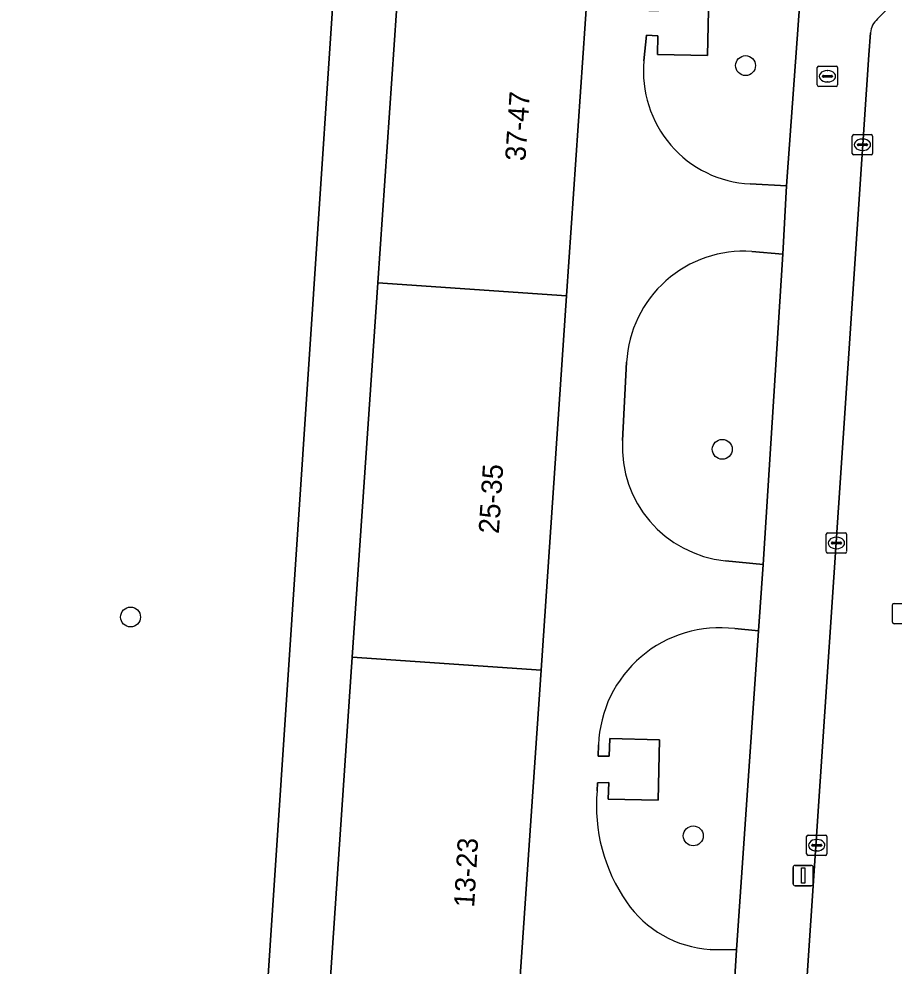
# Model space of a CAD drawing. Extents: x 161848 to 162726, y 385382 to 386521.
# Drawn here: x 162230.99 to 162273.99, y 385418.26 to 385464.81 of the extents above; entities that cross this region are included whole.
import ezdxf

# ---------------------------------------------------------------- set-up
doc = ezdxf.new("R2010")
doc.units = 0
for name, color, linetype in [('IMGEO_Boom', 7, 'Continuous'), ('IMGEO_Brandkraan', 7, 'Continuous'), ('IMGEO_Groenvoorziening', 7, 'Continuous'), ('IMGEO_Kolk', 7, 'Continuous'), ('IMGEO_Lichtmast', 7, 'Continuous'), ('IMGEO_Pand', 7, 'Continuous'), ('IMGEO_Pand_nummerreeks', 7, 'Continuous'), ('IMGEO_Rijbaan_lokaal_open', 7, 'Continuous'), ('IMGEO_Rioolput', 7, 'Continuous'), ('IMGEO_Voetpad_open', 7, 'Continuous')]:
    doc.layers.add(name, color=color, linetype=linetype)

msp = doc.modelspace()

# ---------------------------------------------------------------- linework, layer by layer
at = {"layer": 'IMGEO_Boom'}
for centre in [(162266.695, 385462.519), (162265.549, 385443.66), (162236.471, 385435.417), (162264.124, 385424.661)]:
    msp.add_circle(centre, 0.489, dxfattribs=at)
at = {"layer": 'IMGEO_Brandkraan'}
for p, q in [((162270.218, 385461.567), (162270.218, 385462.419)), ((162270.293, 385462.493), (162271.145, 385462.493)), ((162270.706, 385462.273), (162270.731, 385462.273)), ((162271.219, 385462.419), (162271.219, 385461.567)), ((162270.477, 385461.987), (162270.477, 385461.999)), ((162270.915, 385461.95), (162270.517, 385461.95)), ((162270.52, 385462.036), (162270.918, 385462.036)), ((162270.729, 385461.713), (162270.704, 385461.713)), ((162270.961, 385461.999), (162270.961, 385461.987)), ((162271.145, 385461.493), (162270.293, 385461.493))]:
    msp.add_line(p, q, dxfattribs=at)
for points in [[(162270.218, 385461.567), (162270.218, 385462.419)], [(162270.293, 385462.493), (162271.145, 385462.493)], [(162271.219, 385462.419), (162271.219, 385461.567)], [(162271.145, 385461.493), (162270.293, 385461.493)]]:
    msp.add_lwpolyline(points, dxfattribs=at)
for centre, radius, start, end in [((162270.295, 385462.417), 0.0765, 91.552, 178.448), ((162270.295, 385462.417), 0.0765, 91.552, 178.448), ((162271.143, 385462.417), 0.0765, 1.552, 88.448), ((162271.143, 385462.417), 0.0765, 1.552, 88.448), ((162270.517, 385461.996), 0.0403, 85.8775, 175.7526), ((162270.514, 385461.986), 0.0366, 178.938, 274.7102), ((162270.918, 385461.993), 0.043, 264.8664, 352.4533), ((162270.922, 385461.998), 0.0386, 1.7309, 96.639), ((162270.295, 385461.569), 0.0765, 181.552, 268.448), ((162270.295, 385461.569), 0.0765, 181.552, 268.448), ((162271.143, 385461.569), 0.0765, 271.552, 358.448), ((162271.143, 385461.569), 0.0765, 271.552, 358.448)]:
    msp.add_arc(centre, radius, start, end, dxfattribs=at)
for centre, major_axis, ratio, start_param, end_param in [((162270.705, 385461.993), (-0.387, 0.002), 0.722429, 4.712389, 7.853982), ((162270.73, 385461.993), (-0.39, 0.002), 0.717154, 1.570796, 4.712389)]:
    msp.add_ellipse(centre, major_axis=major_axis, ratio=ratio, start_param=start_param, end_param=end_param, dxfattribs=at)
at = {"layer": 'IMGEO_Groenvoorziening'}
for points in [[(162227.271, 385391.248), (162241.486, 385391.457), (162250.499, 385527.157), (162261.965, 385526.444), (162262.479, 385534.283), (162237.367, 385535.933)], [(162266.924, 385456.7), (162268.704, 385456.607), (162269.753, 385471.068)], [(162262.029, 385466.193), (162261.937, 385465.228), (162262.419, 385465.208), (162262.439, 385466.033), (162264.889, 385465.975), (162264.819, 385463.01), (162262.368, 385463.068), (162262.39, 385463.989), (162261.82, 385464.01), (162261.7, 385462.758)], [(162265.711, 385438.182), (162267.563, 385437.996), (162268.527, 385453.246), (162266.997, 385453.383)], [(162260.848, 385447.937), (162260.642, 385444.097)], [(162264.948, 385419.073), (162266.246, 385419.052), (162267.337, 385434.743)], [(162267.337, 385434.743), (162266.167, 385434.846)], [(162259.467, 385429.143), (162259.45, 385428.574), (162259.999, 385428.573), (162260.02, 385429.446), (162262.468, 385429.388), (162262.397, 385426.41), (162259.949, 385426.468), (162259.968, 385427.283), (162259.41, 385427.271), (162259.398, 385426.87)]]:
    msp.add_lwpolyline(points, dxfattribs=at)
for centre, radius, start, end in [((162267.21, 385462.228), 5.535, 174.5052, 267.0392), ((162266.607, 385447.629), 5.767, 86.1251, 176.9358), ((162266.276, 385443.795), 5.642, 176.936, 264.2555), ((162265.435, 385428.918), 5.973, 82.9641, 177.8444), ((162267.609, 385426.129), 8.244, 174.8464, 214.8948), ((162265.34, 385424.524), 5.465, 214.6978, 265.8847)]:
    msp.add_arc(centre, radius, start, end, dxfattribs=at)
at = {"layer": 'IMGEO_Kolk'}
for p, q in [((162271.938, 385458.203), (162271.938, 385459.055)), ((162272.013, 385459.129), (162272.865, 385459.129)), ((162272.426, 385458.909), (162272.451, 385458.909)), ((162272.939, 385459.055), (162272.939, 385458.203)), ((162272.197, 385458.623), (162272.197, 385458.635)), ((162272.635, 385458.586), (162272.237, 385458.586)), ((162272.24, 385458.672), (162272.638, 385458.672)), ((162272.449, 385458.349), (162272.424, 385458.349)), ((162272.681, 385458.635), (162272.681, 385458.623)), ((162272.865, 385458.129), (162272.013, 385458.129)), ((162270.66, 385438.629), (162270.66, 385439.481)), ((162270.735, 385439.555), (162271.587, 385439.555)), ((162271.148, 385439.335), (162271.173, 385439.335)), ((162271.661, 385439.481), (162271.661, 385438.629)), ((162270.919, 385439.049), (162270.919, 385439.061)), ((162271.357, 385439.012), (162270.959, 385439.012)), ((162270.962, 385439.098), (162271.36, 385439.098)), ((162271.403, 385439.061), (162271.403, 385439.049)), ((162271.587, 385438.555), (162270.735, 385438.555)), ((162271.171, 385438.775), (162271.146, 385438.775)), ((162269.693, 385423.774), (162269.693, 385424.626)), ((162269.768, 385424.7), (162270.62, 385424.7)), ((162270.181, 385424.48), (162270.206, 385424.48)), ((162270.694, 385424.626), (162270.694, 385423.774)), ((162269.952, 385424.194), (162269.952, 385424.206)), ((162270.39, 385424.157), (162269.992, 385424.157)), ((162269.995, 385424.243), (162270.393, 385424.243)), ((162270.204, 385423.92), (162270.179, 385423.92)), ((162270.436, 385424.206), (162270.436, 385424.194)), ((162270.62, 385423.7), (162269.768, 385423.7))]:
    msp.add_line(p, q, dxfattribs=at)
for points in [[(162271.938, 385458.203), (162271.938, 385459.055)], [(162272.013, 385459.129), (162272.865, 385459.129)], [(162272.939, 385459.055), (162272.939, 385458.203)], [(162272.865, 385458.129), (162272.013, 385458.129)], [(162270.66, 385438.629), (162270.66, 385439.481)], [(162270.735, 385439.555), (162271.587, 385439.555)], [(162271.661, 385439.481), (162271.661, 385438.629)], [(162271.587, 385438.555), (162270.735, 385438.555)], [(162269.693, 385423.774), (162269.693, 385424.626)], [(162269.768, 385424.7), (162270.62, 385424.7)], [(162270.694, 385424.626), (162270.694, 385423.774)], [(162270.62, 385423.7), (162269.768, 385423.7)]]:
    msp.add_lwpolyline(points, dxfattribs=at)
for centre, radius, start, end in [((162272.015, 385459.053), 0.0765, 91.552, 178.448), ((162272.015, 385459.053), 0.0765, 91.552, 178.448), ((162272.863, 385459.053), 0.0765, 1.552, 88.448), ((162272.863, 385459.053), 0.0765, 1.552, 88.448), ((162272.237, 385458.632), 0.0403, 85.8775, 175.7526), ((162272.234, 385458.622), 0.0366, 178.938, 274.7102), ((162272.638, 385458.629), 0.043, 264.8664, 352.4533), ((162272.642, 385458.634), 0.0386, 1.7309, 96.639), ((162272.015, 385458.205), 0.0765, 181.552, 268.448), ((162272.015, 385458.205), 0.0765, 181.552, 268.448), ((162272.863, 385458.205), 0.0765, 271.552, 358.448), ((162272.863, 385458.205), 0.0765, 271.552, 358.448), ((162270.737, 385439.479), 0.0765, 91.552, 178.448), ((162270.737, 385439.479), 0.0765, 91.552, 178.448), ((162271.585, 385439.479), 0.0765, 1.552, 88.448), ((162271.585, 385439.479), 0.0765, 1.552, 88.448), ((162270.959, 385439.058), 0.0403, 85.8775, 175.7526), ((162270.956, 385439.048), 0.0366, 178.938, 274.7102), ((162271.36, 385439.055), 0.043, 264.8664, 352.4533), ((162271.364, 385439.06), 0.0386, 1.7309, 96.639), ((162270.737, 385438.631), 0.0765, 181.552, 268.448), ((162270.737, 385438.631), 0.0765, 181.552, 268.448), ((162271.585, 385438.631), 0.0765, 271.552, 358.448), ((162271.585, 385438.631), 0.0765, 271.552, 358.448), ((162269.77, 385424.624), 0.0765, 91.552, 178.448), ((162269.77, 385424.624), 0.0765, 91.552, 178.448), ((162270.618, 385424.624), 0.0765, 1.552, 88.448), ((162270.618, 385424.624), 0.0765, 1.552, 88.448), ((162269.992, 385424.203), 0.0403, 85.8775, 175.7526), ((162269.989, 385424.193), 0.0366, 178.938, 274.7102), ((162270.393, 385424.2), 0.043, 264.8664, 352.4533), ((162270.397, 385424.205), 0.0386, 1.7309, 96.639), ((162269.77, 385423.776), 0.0765, 181.552, 268.448), ((162269.77, 385423.776), 0.0765, 181.552, 268.448), ((162270.618, 385423.776), 0.0765, 271.552, 358.448), ((162270.618, 385423.776), 0.0765, 271.552, 358.448)]:
    msp.add_arc(centre, radius, start, end, dxfattribs=at)
for centre, major_axis, ratio, start_param, end_param in [((162272.425, 385458.629), (-0.387, 0.002), 0.722429, 4.712389, 7.853982), ((162272.45, 385458.629), (-0.39, 0.002), 0.717154, 1.570796, 4.712389), ((162271.147, 385439.055), (-0.387, 0.002), 0.722429, 4.712389, 7.853982), ((162271.172, 385439.055), (-0.39, 0.002), 0.717154, 1.570796, 4.712389), ((162270.18, 385424.2), (-0.387, 0.002), 0.722429, 4.712389, 7.853982), ((162270.205, 385424.2), (-0.39, 0.002), 0.717154, 1.570796, 4.712389)]:
    msp.add_ellipse(centre, major_axis=major_axis, ratio=ratio, start_param=start_param, end_param=end_param, dxfattribs=at)
at = {"layer": 'IMGEO_Lichtmast'}
for p, q in [((162269.03, 385422.309), (162269.03, 385423.109)), ((162269.03, 385423.109), (162269.03, 385422.309)), ((162269.13, 385423.209), (162269.92, 385423.209)), ((162269.92, 385423.209), (162269.13, 385423.209)), ((162270.02, 385423.109), (162270.02, 385422.309)), ((162270.02, 385422.309), (162270.02, 385423.109)), ((162269.92, 385422.209), (162269.13, 385422.209)), ((162269.13, 385422.209), (162269.92, 385422.209))]:
    msp.add_line(p, q, dxfattribs=at)
msp.add_lwpolyline([(162269.45, 385423.084), (162269.6, 385423.084), (162269.6, 385422.334), (162269.45, 385422.334), (162269.45, 385423.084)], dxfattribs=at)
for centre, start, end in [((162269.13, 385423.109), 90, 180), ((162269.13, 385423.109), 90, 180), ((162269.92, 385423.109), 0, 90), ((162269.92, 385423.109), 360, 90), ((162269.13, 385422.309), 180, 270), ((162269.13, 385422.309), 180, 270), ((162269.92, 385422.309), 270, 0), ((162269.92, 385422.309), 270, 0)]:
    msp.add_arc(centre, 0.1, start, end, dxfattribs=at)
at = {"layer": 'IMGEO_Pand'}
for points in [[(162259.156, 385469.606), (162249.879, 385470.239), (162248.624, 385451.841), (162257.902, 385451.209)], [(162257.902, 385451.209), (162248.624, 385451.841), (162247.369, 385433.444), (162256.647, 385432.811)], [(162256.647, 385432.811), (162247.369, 385433.444), (162246.114, 385415.046), (162255.393, 385414.414)]]:
    msp.add_lwpolyline(points, close=True, dxfattribs=at)
at = {"layer": 'IMGEO_Rijbaan_lokaal_open'}
for points in [[(162273.988, 385465.604), (162273.176, 385464.812)], [(162272.835, 385464.128), (162272.75, 385463.047), (162268.862, 385405.077)]]:
    msp.add_lwpolyline(points, dxfattribs=at)
msp.add_arc((162273.826, 385464.061), 0.993, 130.8692, 176.1348, dxfattribs=at)
at = {"layer": 'IMGEO_Rioolput'}
for p, q in [((162273.917, 385435.163), (162273.917, 385436.015)), ((162273.992, 385436.089), (162274.844, 385436.089)), ((162274.844, 385435.089), (162273.992, 385435.089))]:
    msp.add_line(p, q, dxfattribs=at)
for points in [[(162273.917, 385435.163), (162273.917, 385436.015)], [(162273.992, 385436.089), (162274.844, 385436.089)], [(162274.844, 385435.089), (162273.992, 385435.089)]]:
    msp.add_lwpolyline(points, dxfattribs=at)
for centre, start, end in [((162273.994, 385436.013), 91.552, 178.448), ((162273.994, 385436.013), 91.552, 178.448), ((162273.994, 385435.165), 181.552, 268.448), ((162273.994, 385435.165), 181.552, 268.448)]:
    msp.add_arc(centre, 0.0765, start, end, dxfattribs=at)
at = {"layer": 'IMGEO_Voetpad_open'}
for points in [[(162265.497, 385518.248), (162265.529, 385518.79), (162265.893, 385518.768), (162265.834, 385517.933), (162268.677, 385517.734), (162268.891, 385520.791), (162266.048, 385520.989), (162265.98, 385520.017), (162265.602, 385520.039), (162265.961, 385526.178), (162262.952, 385526.381), (162263.466, 385534.217), (162262.479, 385534.283), (162261.965, 385526.444), (162250.499, 385527.157), (162241.486, 385391.457), (162243.197, 385391.482), (162243.301, 385395.075), (162255.477, 385394.425), (162255.343, 385391.66), (162257.257, 385391.689), (162257.254, 385391.956)], [(162273.776, 385531.24), (162273.391, 385525.618), (162272.54, 385510.932), (162272.356, 385507.75), (162271.812, 385500), (162271.222, 385492.992), (162270.894, 385489.82), (162269.853, 385474.089), (162269.753, 385471.068), (162268.704, 385456.607), (162268.527, 385453.246), (162267.563, 385437.996), (162267.337, 385434.743), (162266.246, 385419.052), (162266.047, 385415.86), (162265.301, 385404.029), (162265.103, 385400.915), (162264.862, 385397.867), (162264.665, 385394.839)], [(162259.156, 385469.606), (162257.902, 385451.209), (162256.647, 385432.811), (162255.393, 385414.414), (162254.138, 385396.016), (162243.064, 385396.773), (162243.085, 385397.073), (162244.083, 385397.005), (162244.88, 385396.95), (162246.114, 385415.046), (162247.369, 385433.444), (162248.624, 385451.841), (162249.879, 385470.239)], [(162261.7, 385462.758), (162261.82, 385464.01), (162262.39, 385463.989), (162262.368, 385463.068), (162264.819, 385463.01), (162264.889, 385465.975), (162262.439, 385466.033), (162262.419, 385465.208), (162261.937, 385465.228), (162262.029, 385466.193)], [(162273.176, 385464.812), (162273.988, 385465.604)], [(162272.75, 385463.047), (162272.835, 385464.128)], [(162268.862, 385405.077), (162272.75, 385463.047)], [(162266.997, 385453.383), (162268.527, 385453.246), (162268.704, 385456.607), (162266.924, 385456.7)], [(162260.642, 385444.097), (162260.848, 385447.937)], [(162266.167, 385434.846), (162267.337, 385434.743), (162267.563, 385437.996), (162265.711, 385438.182)], [(162259.398, 385426.87), (162259.41, 385427.271), (162259.968, 385427.283), (162259.949, 385426.468), (162262.397, 385426.41), (162262.468, 385429.388), (162260.02, 385429.446), (162259.999, 385428.573), (162259.45, 385428.574), (162259.467, 385429.143)], [(162264.6, 385416.009), (162266.047, 385415.86), (162266.246, 385419.052), (162264.948, 385419.073)]]:
    msp.add_lwpolyline(points, dxfattribs=at)
for centre, radius, start, end in [((162273.826, 385464.061), 0.993, 130.8692, 176.1348), ((162267.21, 385462.228), 5.535, 174.5052, 267.0392), ((162266.607, 385447.629), 5.767, 86.1251, 176.9358), ((162266.276, 385443.795), 5.642, 176.936, 264.2555), ((162265.435, 385428.918), 5.973, 82.9641, 177.8444), ((162267.609, 385426.129), 8.244, 174.8464, 214.8948), ((162265.34, 385424.524), 5.465, 214.6978, 265.8847)]:
    msp.add_arc(centre, radius, start, end, dxfattribs=at)

# ---------------------------------------------------------------- texts
at = {"layer": 'IMGEO_Pand_nummerreeks'}
for s, rotation, p in [('37-47', 86.1936, (162255.873, 385457.802)), ('25-35', 86.3012, (162254.569, 385439.488)), ('13-23', 86.6872, (162253.356, 385421.123))]:
    msp.add_text(s, height=1, rotation=rotation, dxfattribs=at).set_placement(p)

doc.saveas('drawing.dxf')
